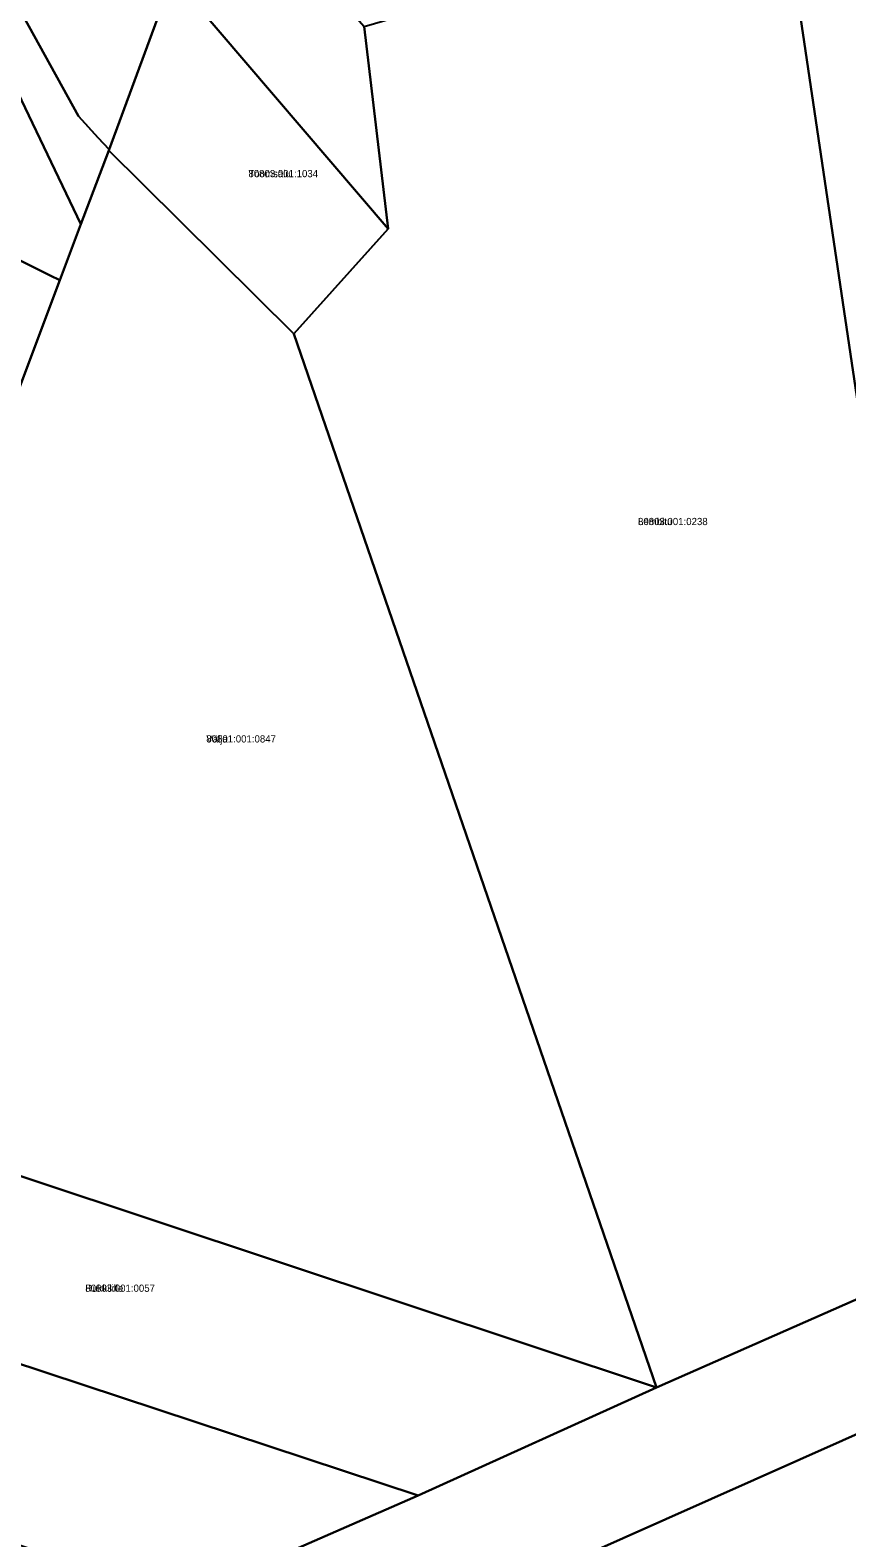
# Model space of a CAD drawing. Extents: x 524000 to 564260, y 6469338 to 6496391.
# Drawn here: x 539632.9 to 539802.9, y 6474807.9 to 6475121.9 of the extents above; entities that cross this region are included whole.
import ezdxf

# ---------------------------------------------------------------- set-up
doc = ezdxf.new("R2010")
doc.units = 0
for name, color, linetype in [('L_AADRESS', 7, 'Continuous'), ('PIIR', 7, 'Continuous'), ('TUNNUS', 7, 'Continuous')]:
    doc.layers.add(name, color=color, linetype=linetype)

msp = doc.modelspace()

# ---------------------------------------------------------------- linework, layer by layer
at = {"layer": 'PIIR'}
for points in [[(539831.16, 6474869.16), (539782.58, 6475196.75), (539781.45, 6475203.72), (539790.66, 6475217.23), (539807.6, 6475242.18), (539823, 6475264.86), (539826.64, 6475263.44), (539876.07, 6475242.79), (539920.24, 6475224.35), (539955.56, 6475209.05), (539974.27, 6474933.88), (539974.31, 6474933.36)], [(539605.37, 6475156.48), (539549.38, 6475215.78), (539554.03, 6475218.82), (539561.15, 6475210.35), (539597.66, 6475177.19), (539603.22, 6475172.2), (539612.5, 6475163.41), (539621.61, 6475144.62), (539625.52, 6475135.5), (539642.98, 6475104.01), (539647.08, 6475099.52), (539649.32, 6475097.06), (539649.25, 6475096.88), (539643.46, 6475081.48), (539641.9, 6475084.73), (539626.35, 6475117.08), (539619.33, 6475130.28)], [(539707.43, 6475080.55), (539702.45, 6475122.64), (539735.2, 6475132.23), (539717.35, 6475170.84), (539715.66, 6475174.83), (539733.3, 6475179.78), (539733.34, 6475179.79), (539744.47, 6475182.97), (539749.04, 6475184.26), (539757.47, 6475186.65), (539757.84, 6475186.75), (539764.82, 6475188.64), (539768.02, 6475189.95), (539771.96, 6475192.14), (539774.49, 6475194.19), (539775.29, 6475195.12), (539776.71, 6475196.77), (539781.45, 6475203.72), (539782.58, 6475196.75), (539831.16, 6474869.16), (539763.32, 6474839.28), (539687.76, 6475058.65)], [(539603.22, 6475172.2), (539597.66, 6475177.19), (539615.58, 6475191.51), (539659.37, 6475138.39), (539662.79, 6475134.25), (539662.99, 6475134.01), (539662.56, 6475132.85), (539649.32, 6475097.06), (539647.08, 6475099.52), (539642.98, 6475104.01), (539625.52, 6475135.5), (539634.4, 6475140.4), (539630.3, 6475149.54), (539621.61, 6475144.62), (539612.5, 6475163.41), (539619.25, 6475168.07), (539612.97, 6475176.53)], [(539662.56, 6475132.85), (539662.99, 6475134.01), (539663.04, 6475134.13), (539664.06, 6475136.89), (539665.98, 6475142.03), (539670.93, 6475154.18), (539671.93, 6475156.39), (539672.2, 6475156.98), (539674.89, 6475154.13), (539702.45, 6475122.64), (539707.43, 6475080.55), (539665.86, 6475129.17)], [(539649.32, 6475097.06), (539662.56, 6475132.85), (539665.86, 6475129.17), (539707.43, 6475080.55), (539687.76, 6475058.65), (539656.29, 6475089.89), (539649.25, 6475096.88)], [(539586.17, 6475096.34), (539626.35, 6475117.08), (539641.9, 6475084.73), (539643.46, 6475081.48), (539639.08, 6475069.84), (539637.08, 6475070.84)], [(539568.44, 6475087.13), (539586.17, 6475096.34), (539637.08, 6475070.84), (539639.08, 6475069.84), (539614.81, 6475005.29), (539610.58, 6475012.76)], [(539649.25, 6475096.88), (539656.29, 6475089.89), (539687.76, 6475058.65), (539763.32, 6474839.28), (539580.15, 6474900.15), (539575.81, 6474901.59), (539614.81, 6475005.29), (539639.08, 6475069.84), (539643.46, 6475081.48)], [(539562.61, 6474866.67), (539575.81, 6474901.59), (539580.15, 6474900.15), (539763.32, 6474839.28), (539713.71, 6474816.76), (539566.31, 6474865.45)], [(539701.19, 6474783.29), (539893.99, 6474869.19), (539975.22, 6474793.42), (539854.6, 6474732.47)], [(539553.84, 6474831.7), (539549.89, 6474833.01), (539562.61, 6474866.67), (539566.31, 6474865.45), (539713.71, 6474816.76), (539664.49, 6474795.23)]]:
    msp.add_lwpolyline(points, close=True, dxfattribs=at)
for points in [[(539664.49, 6474795.23), (539713.71, 6474816.76), (539763.32, 6474839.28), (539831.16, 6474869.16), (539974.31, 6474933.36), (540037.14, 6474961.39), (540098.24, 6474988.66), (540129.14, 6475002.37), (540171.52, 6475021.24), (540215.02, 6475040.81), (540249.92, 6475056.62), (540300.8, 6475079.71), (540346.44, 6475100.61), (540376.25, 6475114.25), (540400.34, 6475125.32), (540421.33, 6475134.6), (540421.41, 6475134.67), (540646.33, 6475239.15)], [(540566.11, 6475173.13), (540429.85, 6475109.84), (540396.52, 6475094.03), (540387.28, 6475089.58), (540334.48, 6475065.17), (540308.17, 6475053), (540286.92, 6475043.59), (540237.44, 6475021.69), (540185.66, 6474998.77), (540132.01, 6474974.98), (540118.13, 6474968.95), (539982.51, 6474909.51), (539893.99, 6474869.19), (539701.19, 6474783.29)]]:
    msp.add_lwpolyline(points, dxfattribs=at)

# ---------------------------------------------------------------- texts
at = {"layer": 'L_AADRESS'}
for s, p in [('Toomsalu', (539678.34, 6475091.29)), ('Lembitu', (539759.46, 6475018.84)), ('Välja', (539669.57, 6474973.57)), ('Rukkilille', (539644.38, 6474859.18))]:
    msp.add_text(s, height=1.5, dxfattribs=at).set_placement(p)
at = {"layer": 'TUNNUS'}
for s, p in [('80803:001:1034', (539678.34, 6475091.29)), ('80803:001:0238', (539759.46, 6475018.84)), ('80801:001:0847', (539669.57, 6474973.57)), ('80803:001:0057', (539644.38, 6474859.18))]:
    msp.add_text(s, height=1.5, dxfattribs=at).set_placement(p)

doc.saveas('drawing.dxf')
